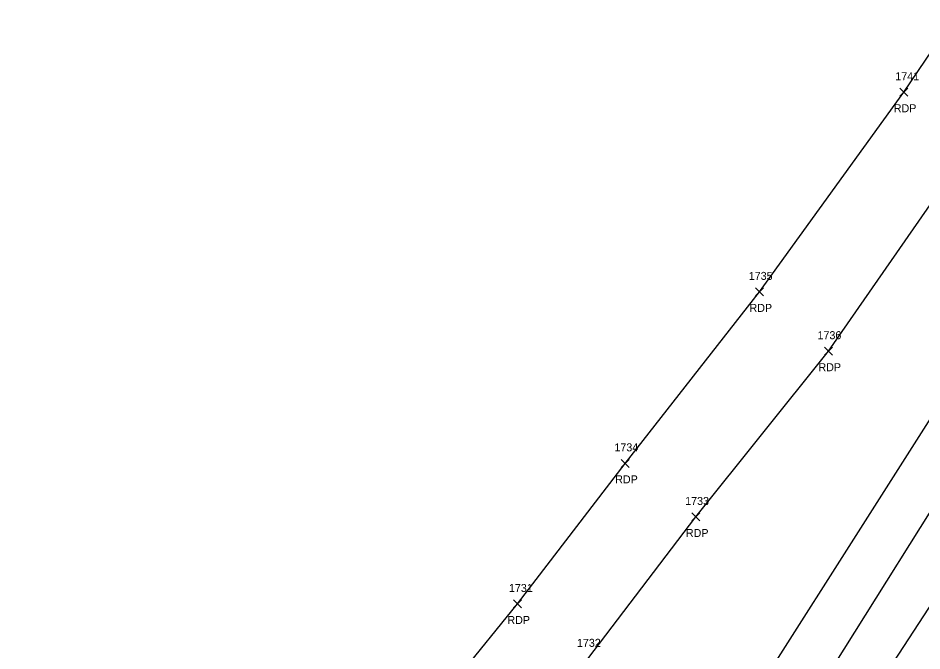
# Model space of a CAD drawing. Extents: x 1508122 to 1515053, y 865012 to 875267.
# Drawn here: x 1511162.4 to 1511388.1, y 869944.5 to 870102.7 of the extents above; entities that cross this region are included whole.
import ezdxf

# ---------------------------------------------------------------- set-up
doc = ezdxf.new("R2010")
doc.units = 0
for name, color, linetype in [('LFNC', 7, 'Continuous'), ('P_A', 7, 'Continuous'), ('P_I', 7, 'Continuous'), ('P_TIC', 7, 'Continuous'), ('PET', 7, 'Continuous'), ('R_I', 7, 'Continuous'), ('RRB', 7, 'Continuous')]:
    doc.layers.add(name, color=color, linetype=linetype)

msp = doc.modelspace()

# ---------------------------------------------------------------- linework, layer by layer
at = {"layer": 'LFNC'}
msp.add_lwpolyline([(1511290.91, 869849.18), (1511327.8, 869904.4), (1511394.98, 870009.98), (1511425.13, 870055.54), (1511455.87, 870105.19), (1511491.53, 870158.85), (1511535.01, 870223.89), (1511575.2, 870287.48), (1511608.77, 870338.28), (1511623.7, 870361.63)], dxfattribs=at)
at = {"layer": 'P_TIC'}
for points in [[(1511382.61, 870083.12), (1511384.61, 870085.12)], [(1511384.61, 870083.12), (1511382.61, 870085.12)], [(1511346.57, 870033.24), (1511348.57, 870035.24)], [(1511348.57, 870033.24), (1511346.57, 870035.24)], [(1511363.79, 870018.42), (1511365.79, 870020.42)], [(1511365.79, 870018.42), (1511363.79, 870020.42)], [(1511313.02, 869990.4), (1511315.02, 869992.4)], [(1511315.02, 869990.4), (1511313.02, 869992.4)], [(1511330.68, 869977), (1511332.68, 869979)], [(1511332.68, 869977), (1511330.68, 869979)], [(1511286.1, 869955.26), (1511288.1, 869957.26)], [(1511288.1, 869955.26), (1511286.1, 869957.26)]]:
    msp.add_lwpolyline(points, dxfattribs=at)
at = {"layer": 'PET'}
for points in [[(1510904.69, 869375.99), (1510944.1, 869457.65), (1510981.65, 869532.24), (1511024.08, 869604.47), (1511042.96, 869631.7), (1511093.88, 869696.57), (1511130.92, 869743.2), (1511165.56, 869789.59), (1511207.17, 869847.2), (1511226.31, 869876.38), (1511258, 869920.32), (1511287.1, 869956.26), (1511314.02, 869991.4), (1511347.57, 870034.24), (1511383.61, 870084.12), (1511412.26, 870126.56)], [(1510922.16, 869361.87), (1510963.34, 869449.46), (1511001.23, 869521.95), (1511042, 869590.98), (1511060.37, 869618.22), (1511110.19, 869682.89), (1511147.27, 869729.24), (1511182.11, 869775.48), (1511226.38, 869838.36), (1511244.52, 869863.34), (1511275.64, 869907.23), (1511304.66, 869942.55), (1511331.68, 869978), (1511364.79, 870019.42), (1511401.8, 870072.69), (1511429.85, 870113.63)]]:
    msp.add_lwpolyline(points, dxfattribs=at)
at = {"layer": 'RRB'}
for points in [[(1510567.62, 868706.56), (1510590.3, 868741.33), (1510641.58, 868821.14), (1510694.12, 868904.03), (1510737.34, 868971.49), (1510810.55, 869083.19), (1510862.56, 869162.99), (1510923.65, 869257.51), (1510962.65, 869316.48), (1511003.03, 869380.52), (1511033.75, 869429.1), (1511076.21, 869490.94), (1511122.4, 869564.68), (1511156.76, 869618.82), (1511179.37, 869653.25), (1511213.93, 869708.42), (1511264.74, 869787.25), (1511286.05, 869815.23), (1511349.66, 869914.55), (1511393.09, 869983.89), (1511436.1, 870048.65), (1511490.68, 870132.35)], [(1510600.6, 868735.49), (1510651.55, 868814.96), (1510704.78, 868897.68), (1510748.11, 868964.85), (1510821.21, 869076.32), (1510873.49, 869156.69), (1510934.14, 869250.38), (1510973.56, 869310.54), (1511014.14, 869373.22), (1511046.88, 869423.36), (1511086.93, 869485.24), (1511132.78, 869556.33), (1511168.28, 869611.72), (1511189.07, 869644.73), (1511224.88, 869702.41), (1511269.99, 869771.64), (1511301.83, 869821.13), (1511359.57, 869908.74), (1511403.78, 869976.54), (1511445.67, 870042.93), (1511499.01, 870126.5)]]:
    msp.add_lwpolyline(points, dxfattribs=at)

# ---------------------------------------------------------------- texts
at = {"layer": 'P_A'}
for p in [(1511381.1, 870079.12), (1511345.06, 870029.24), (1511362.28, 870014.42), (1511311.51, 869986.4), (1511329.17, 869973), (1511284.58, 869951.26)]:
    msp.add_text('RDP', height=2, dxfattribs=at).set_placement(p)
at = {"layer": 'P_I'}
for s, p in [('1741', (1511381.48, 870087.12)), ('1735', (1511344.88, 870037.24)), ('1736', (1511362.05, 870022.42)), ('1734', (1511311.32, 869994.4)), ('1733', (1511328.99, 869981)), ('1731', (1511284.97, 869959.26)), ('1732', (1511301.96, 869945.55))]:
    msp.add_text(s, height=2, dxfattribs=at).set_placement(p)
at = {"layer": 'R_I'}
msp.add_text('1732', height=2, dxfattribs=at).set_placement((1511301.96, 869945.55))

doc.saveas('drawing.dxf')
